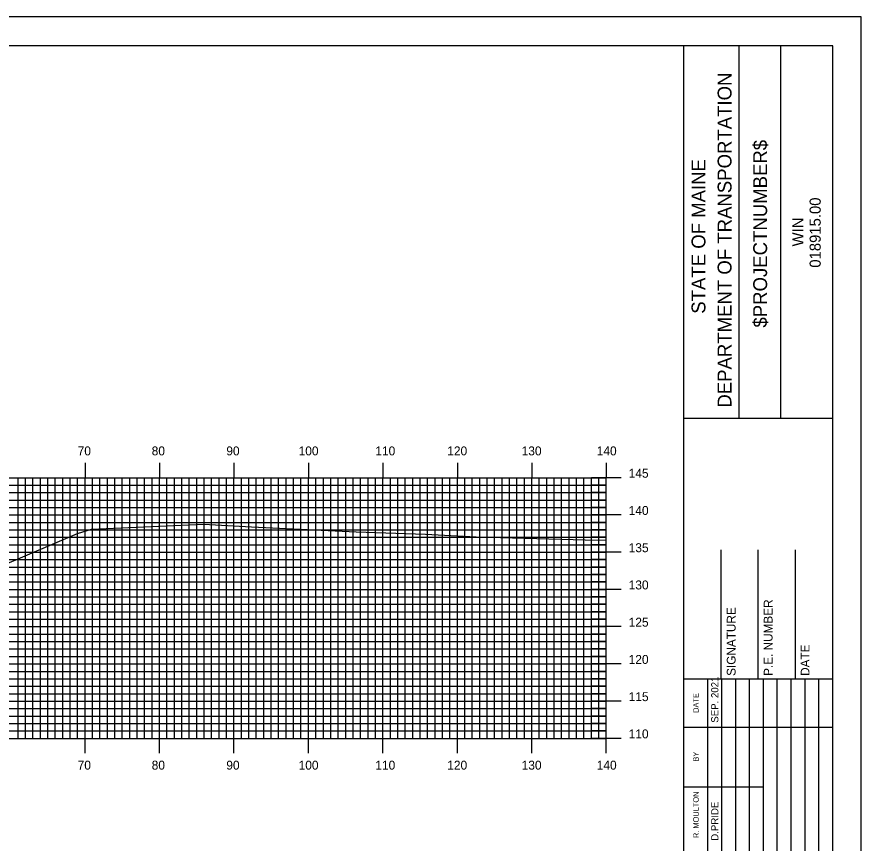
# Model space of a CAD drawing. Extents: x 852934 to 853277, y 364661 to 364881.
# Drawn here: x 853160.6 to 853274, y 364770.3 to 364881.3 of the extents above; entities that cross this region are included whole.
import ezdxf

# ---------------------------------------------------------------- set-up
doc = ezdxf.new("R2010")
doc.units = 0
for name, color, linetype in [('BORDER', 7, 'Continuous'), ('H_V ANNOTATION', 7, 'Continuous'), ('MAJOR', 7, 'Continuous'), ('MINOR', 7, 'Continuous'), ('PLOT BOUNDARY', 7, 'Continuous'), ('S_Roadway_Centerline', 7, 'Continuous')]:
    doc.layers.add(name, color=color, linetype=linetype)

msp = doc.modelspace()

# ---------------------------------------------------------------- linework, layer by layer
at = {"layer": 'BORDER'}
for p, q in [((853250.18, 364667.37), (853250.18, 364877.37)), ((853257.64, 364827.36), (853257.64, 364877.36)), ((853263.23, 364827.36), (853263.23, 364877.36)), ((853250.18, 364827.36), (853270.18, 364827.36)), ((853255.18, 364792.38), (853255.18, 364809.67)), ((853260.18, 364792.38), (853260.18, 364809.67)), ((853265.18, 364792.38), (853265.18, 364809.67)), ((853250.18, 364792.38), (853270.18, 364792.38))]:
    msp.add_line(p, q, dxfattribs=at)
msp.add_lwpolyline([(852950.18, 364667.37), (853270.18, 364667.37), (853270.18, 364877.37), (852950.18, 364877.37)], close=True, dxfattribs=at)
for points in [[(853253.41, 364785.88), (853253.41, 364792.38)], [(853255.28, 364757.38), (853255.28, 364792.38)], [(853257.14, 364792.38), (853257.14, 364757.38)], [(853259, 364757.38), (853259, 364792.38)], [(853260.87, 364757.38), (853260.87, 364792.38)], [(853262.73, 364757.38), (853262.73, 364792.38)], [(853264.59, 364757.38), (853264.59, 364792.38)], [(853266.46, 364757.38), (853266.46, 364792.38)], [(853268.32, 364757.38), (853268.32, 364792.38)], [(853253.41, 364757.38), (853253.41, 364790.96)], [(853250.18, 364785.88), (853270.18, 364785.88)], [(853250.18, 364777.88), (853253.41, 364777.88)], [(853253.41, 364777.88), (853260.86, 364777.88)]]:
    msp.add_lwpolyline(points, dxfattribs=at)
at = {"layer": 'MAJOR'}
for p, q in [((853169.78, 364821.37), (853169.78, 364819.37)), ((853179.78, 364821.37), (853179.78, 364819.37)), ((853189.78, 364821.37), (853189.78, 364819.37)), ((853199.78, 364821.37), (853199.78, 364819.37)), ((853209.78, 364821.37), (853209.78, 364819.37)), ((853219.78, 364821.37), (853219.78, 364819.37)), ((853229.78, 364821.37), (853229.78, 364819.37)), ((853239.78, 364821.37), (853239.78, 364819.37)), ((852959.78, 364819.37), (853239.78, 364819.37)), ((852959.78, 364819.37), (853239.78, 364819.37)), ((853169.78, 364784.37), (853169.78, 364819.37)), ((853179.78, 364784.37), (853179.78, 364819.37)), ((853189.78, 364784.37), (853189.78, 364819.37)), ((853199.78, 364784.37), (853199.78, 364819.37)), ((853209.78, 364784.37), (853209.78, 364819.37)), ((853219.78, 364784.37), (853219.78, 364819.37)), ((853229.78, 364784.37), (853229.78, 364819.37)), ((853241.79, 364819.37), (853237.78, 364819.37)), ((853239.78, 364784.37), (853239.78, 364819.37)), ((853239.78, 364784.37), (853239.78, 364819.37)), ((852959.78, 364814.37), (853239.78, 364814.37)), ((853241.79, 364814.37), (853237.78, 364814.37)), ((852959.78, 364809.37), (853239.78, 364809.37)), ((853241.79, 364809.37), (853237.78, 364809.37)), ((852959.78, 364804.37), (853239.78, 364804.37)), ((853241.79, 364804.37), (853237.78, 364804.37)), ((852959.78, 364799.37), (853239.78, 364799.37)), ((853241.79, 364799.37), (853237.78, 364799.37)), ((852959.78, 364794.37), (853239.78, 364794.37)), ((853241.79, 364794.37), (853237.78, 364794.37)), ((852959.78, 364789.37), (853239.78, 364789.37)), ((853241.79, 364789.37), (853237.78, 364789.37)), ((852959.78, 364784.37), (853239.78, 364784.37)), ((852959.78, 364784.37), (853239.78, 364784.37)), ((853169.78, 364782.37), (853169.78, 364784.37)), ((853179.78, 364782.37), (853179.78, 364784.37)), ((853189.78, 364782.37), (853189.78, 364784.37)), ((853199.78, 364782.37), (853199.78, 364784.37)), ((853209.78, 364782.37), (853209.78, 364784.37)), ((853219.78, 364782.37), (853219.78, 364784.37)), ((853229.78, 364782.37), (853229.78, 364784.37)), ((853241.79, 364784.37), (853237.78, 364784.37)), ((853239.78, 364782.37), (853239.78, 364784.37))]:
    msp.add_line(p, q, dxfattribs=at)
at = {"layer": 'MINOR'}
for p, q in [((853160.78, 364784.37), (853160.78, 364819.37)), ((853161.78, 364784.37), (853161.78, 364819.37)), ((853162.78, 364784.37), (853162.78, 364819.37)), ((853163.78, 364784.37), (853163.78, 364819.37)), ((853164.78, 364784.37), (853164.78, 364819.37)), ((853165.78, 364784.37), (853165.78, 364819.37)), ((853166.78, 364784.37), (853166.78, 364819.37)), ((853167.78, 364784.37), (853167.78, 364819.37)), ((853168.78, 364784.37), (853168.78, 364819.37)), ((853170.78, 364784.37), (853170.78, 364819.37)), ((853171.78, 364784.37), (853171.78, 364819.37)), ((853172.78, 364784.37), (853172.78, 364819.37)), ((853173.78, 364784.37), (853173.78, 364819.37)), ((853174.78, 364784.37), (853174.78, 364819.37)), ((853175.78, 364784.37), (853175.78, 364819.37)), ((853176.78, 364784.37), (853176.78, 364819.37)), ((853177.78, 364784.37), (853177.78, 364819.37)), ((853178.78, 364784.37), (853178.78, 364819.37)), ((853180.78, 364784.37), (853180.78, 364819.37)), ((853181.78, 364784.37), (853181.78, 364819.37)), ((853182.78, 364784.37), (853182.78, 364819.37)), ((853183.78, 364784.37), (853183.78, 364819.37)), ((853184.78, 364784.37), (853184.78, 364819.37)), ((853185.78, 364784.37), (853185.78, 364819.37)), ((853186.78, 364784.37), (853186.78, 364819.37)), ((853187.78, 364784.37), (853187.78, 364819.37)), ((853188.78, 364784.37), (853188.78, 364819.37)), ((853190.78, 364784.37), (853190.78, 364819.37)), ((853191.78, 364784.37), (853191.78, 364819.37)), ((853192.78, 364784.37), (853192.78, 364819.37)), ((853193.78, 364784.37), (853193.78, 364819.37)), ((853194.78, 364784.37), (853194.78, 364819.37)), ((853195.78, 364784.37), (853195.78, 364819.37)), ((853196.78, 364784.37), (853196.78, 364819.37)), ((853197.78, 364784.37), (853197.78, 364819.37)), ((853198.78, 364784.37), (853198.78, 364819.37)), ((853200.78, 364784.37), (853200.78, 364819.37)), ((853201.78, 364784.37), (853201.78, 364819.37)), ((853202.78, 364784.37), (853202.78, 364819.37)), ((853203.78, 364784.37), (853203.78, 364819.37)), ((853204.78, 364784.37), (853204.78, 364819.37)), ((853205.78, 364784.37), (853205.78, 364819.37)), ((853206.78, 364784.37), (853206.78, 364819.37)), ((853207.78, 364784.37), (853207.78, 364819.37)), ((853208.78, 364784.37), (853208.78, 364819.37)), ((853210.78, 364784.37), (853210.78, 364819.37)), ((853211.78, 364784.37), (853211.78, 364819.37)), ((853212.78, 364784.37), (853212.78, 364819.37)), ((853213.78, 364784.37), (853213.78, 364819.37)), ((853214.78, 364784.37), (853214.78, 364819.37)), ((853215.78, 364784.37), (853215.78, 364819.37)), ((853216.78, 364784.37), (853216.78, 364819.37)), ((853217.78, 364784.37), (853217.78, 364819.37)), ((853218.78, 364784.37), (853218.78, 364819.37)), ((853220.78, 364784.37), (853220.78, 364819.37)), ((853221.78, 364784.37), (853221.78, 364819.37)), ((853222.78, 364784.37), (853222.78, 364819.37)), ((853223.78, 364784.37), (853223.78, 364819.37)), ((853224.78, 364784.37), (853224.78, 364819.37)), ((853225.78, 364784.37), (853225.78, 364819.37)), ((853226.78, 364784.37), (853226.78, 364819.37)), ((853227.78, 364784.37), (853227.78, 364819.37)), ((853228.78, 364784.37), (853228.78, 364819.37)), ((853230.78, 364784.37), (853230.78, 364819.37)), ((853231.78, 364784.37), (853231.78, 364819.37)), ((853232.78, 364784.37), (853232.78, 364819.37)), ((853233.78, 364784.37), (853233.78, 364819.37)), ((853234.78, 364784.37), (853234.78, 364819.37)), ((853235.78, 364784.37), (853235.78, 364819.37)), ((853236.78, 364784.37), (853236.78, 364819.37)), ((853237.78, 364784.37), (853237.78, 364819.37)), ((853238.78, 364784.37), (853238.78, 364819.37)), ((852959.78, 364818.37), (853239.78, 364818.37)), ((853239.78, 364818.37), (853237.78, 364818.37)), ((852959.78, 364817.37), (853239.78, 364817.37)), ((853239.78, 364817.37), (853237.78, 364817.37)), ((852959.78, 364816.37), (853239.78, 364816.37)), ((852959.78, 364815.37), (853239.78, 364815.37)), ((853239.78, 364816.37), (853237.78, 364816.37)), ((853239.78, 364815.37), (853237.78, 364815.37)), ((852959.78, 364813.37), (853239.78, 364813.37)), ((853239.78, 364813.37), (853237.78, 364813.37)), ((852959.78, 364812.37), (853239.78, 364812.37)), ((853239.78, 364812.37), (853237.78, 364812.37)), ((852959.78, 364811.37), (853239.78, 364811.37)), ((853239.78, 364811.37), (853237.78, 364811.37)), ((852959.78, 364810.37), (853239.78, 364810.37)), ((853239.78, 364810.37), (853237.78, 364810.37)), ((852959.78, 364808.37), (853239.78, 364808.37)), ((853239.78, 364808.37), (853237.78, 364808.37)), ((852959.78, 364807.37), (853239.78, 364807.37)), ((852959.78, 364806.37), (853239.78, 364806.37)), ((853239.78, 364807.37), (853237.78, 364807.37)), ((853239.78, 364806.37), (853237.78, 364806.37)), ((852959.78, 364805.37), (853239.78, 364805.37)), ((853239.78, 364805.37), (853237.78, 364805.37)), ((852959.78, 364803.37), (853239.78, 364803.37)), ((853239.78, 364803.37), (853237.78, 364803.37)), ((852959.78, 364802.37), (853239.78, 364802.37)), ((853239.78, 364802.37), (853237.78, 364802.37)), ((852959.78, 364801.37), (853239.78, 364801.37)), ((853239.78, 364801.37), (853237.78, 364801.37)), ((852959.78, 364800.37), (853239.78, 364800.37)), ((853239.78, 364800.37), (853237.78, 364800.37)), ((852959.78, 364798.37), (853239.78, 364798.37)), ((853239.78, 364798.37), (853237.78, 364798.37)), ((852959.78, 364797.37), (853239.78, 364797.37)), ((853239.78, 364797.37), (853237.78, 364797.37)), ((852959.78, 364796.37), (853239.78, 364796.37)), ((853239.78, 364796.37), (853237.78, 364796.37)), ((852959.78, 364795.37), (853239.78, 364795.37)), ((853239.78, 364795.37), (853237.78, 364795.37)), ((852959.78, 364793.37), (853239.78, 364793.37)), ((853239.78, 364793.37), (853237.78, 364793.37)), ((852959.78, 364792.37), (853239.78, 364792.37)), ((853239.78, 364792.37), (853237.78, 364792.37)), ((852959.78, 364791.37), (853239.78, 364791.37)), ((853239.78, 364791.37), (853237.78, 364791.37)), ((852959.78, 364790.37), (853239.78, 364790.37)), ((853239.78, 364790.37), (853237.78, 364790.37)), ((852959.78, 364788.37), (853239.78, 364788.37)), ((853239.78, 364788.37), (853237.78, 364788.37)), ((852959.78, 364787.37), (853239.78, 364787.37)), ((853239.78, 364787.37), (853237.78, 364787.37)), ((852959.78, 364786.37), (853239.78, 364786.37)), ((853239.78, 364786.37), (853237.78, 364786.37)), ((852959.78, 364785.37), (853239.78, 364785.37)), ((853239.78, 364785.37), (853237.78, 364785.37))]:
    msp.add_line(p, q, dxfattribs=at)
at = {"layer": 'PLOT BOUNDARY'}
msp.add_lwpolyline([(852933.99, 364661.25), (853273.99, 364661.25), (853273.99, 364881.25), (852933.99, 364881.25)], close=True, dxfattribs=at)
at = {"layer": 'S_Roadway_Centerline'}
msp.add_lwpolyline([(853158.35, 364807.45), (853168.78, 364811.88), (853170.64, 364812.46), (853172.62, 364812.53), (853185.69, 364813.12), (853192.14, 364812.78), (853206.2, 364812.12), (853215.49, 364811.78), (853222.3, 364811.43), (853236.92, 364811.02), (853239.78, 364810.98)], dxfattribs=at)

# ---------------------------------------------------------------- texts
at = {"layer": 'BORDER'}
for s, height, p in [('DEPARTMENT OF TRANSPORTATION', 1.8635, (853256.59, 364828.78)), ('$PROJECTNUMBER$', 1.8635, (853261.37, 364839.53)), ('STATE OF MAINE', 1.8635, (853253.09, 364841.39)), ('018915.00', 1.491, (853268.57, 364847.57)), ('WIN', 1.491, (853266.25, 364850.43)), ('P.E. NUMBER', 1.1811, (853262.1, 364792.76)), ('SIGNATURE', 1.181, (853257.14, 364792.76)), ('DATE', 1.181, (853267.06, 364792.76)), ('SEP. 2021', 0.969, (853254.83, 364786.47)), ('DATE', 0.743, (853252.19, 364787.79)), ('BY', 0.743, (853252.19, 364781.25)), ('R. MOULTON', 0.745, (853252.19, 364770.98)), ('D.PRIDE', 0.969, (853254.83, 364770.62))]:
    msp.add_text(s, height=height, rotation=90, dxfattribs=at).set_placement(p)
at = {"layer": 'H_V ANNOTATION'}
for s, p in [('70', (853168.79, 364822.37)), ('80', (853178.73, 364822.37)), ('90', (853188.75, 364822.37)), ('100', (853198.46, 364822.37)), ('110', (853208.76, 364822.37)), ('120', (853218.42, 364822.37)), ('130', (853228.41, 364822.37)), ('140', (853238.49, 364822.37)), ('145', (853242.78, 364819.37)), ('140', (853242.78, 364814.37)), ('135', (853242.78, 364809.37)), ('130', (853242.78, 364804.37)), ('125', (853242.78, 364799.37)), ('120', (853242.78, 364794.37)), ('115', (853242.78, 364789.37)), ('110', (853242.78, 364784.37)), ('70', (853168.79, 364780.17)), ('80', (853178.73, 364780.17)), ('90', (853188.75, 364780.17)), ('100', (853198.46, 364780.17)), ('110', (853208.76, 364780.17)), ('120', (853218.42, 364780.17)), ('130', (853228.41, 364780.17)), ('140', (853238.49, 364780.17))]:
    msp.add_text(s, height=1.2, dxfattribs=at).set_placement(p)

doc.saveas('drawing.dxf')
